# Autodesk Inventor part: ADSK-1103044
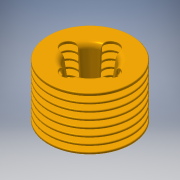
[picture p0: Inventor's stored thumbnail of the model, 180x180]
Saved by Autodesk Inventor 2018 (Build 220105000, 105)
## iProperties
Shininess: 41.0
Length Units: 11272
Angle Units: 11279
Time Units: 11290
Mass Units: 11286
Length Display Precision: 4
Angle Display Precision: 2
Compacted: True
Created: 2000-07
Part Number: ADSK-1103044
Document SubType Name: Modeling
Description: ENGINE HEAD
Mass: 37.1194 g
Surface Area: 215.954 cm^2
Volume: 13.6972 cm^3
Density: 2.71 g/cm^3
Material: Aluminum-6061
Appearance: Yellow
Density: 0.0
Volumn: 0.0
Area: 0.0
PropertySet Name: Model Information
Control State: 0
Master: False
Checked Out: False
Author: Autodesk, Inc.
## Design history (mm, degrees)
node "Revolution1" dims "d6" = 90 deg
  sketch "Sketch2"
    geometry: L1 (17.699, 35.694)-(17.699, 61.094); L2 (17.699, 61.094)-(-5.161, 61.094); L3 (-5.161, 31.884)-(2.459, 31.884); L4 (2.459, 31.884)-(2.459, 35.694); L5 (2.459, 35.694)-(17.699, 35.694); L6 (-5.161, 61.094)-(-5.161, 31.884)
    constraints: 12 end point, 4 perpendicular, 1 parallel, 1 vertical, 1 other
    dimensions: "d0" = 45.72 diameter of L2.end L1; "d1" = 30.48 diameter of L4 L1; "d3" = 29.21 distance between parallel lines of L2 L3; "d5" = 3.81 distance of L3.end L4.end
workaxis "Work Axis1"
workplane "Work Plane1"
workplane "Work Plane3"
node "Revolution2" dims "d12" = 90 deg
  sketch "Sketch3"
    geometry: L1 (0, -20.447)-(0, 20.447) reference; L2 (15.24, -10.795)-(-15.24, -10.795) reference; L3 (-5.999, -10.795)-(-5.999, -8.255); L4 (-5.999, -8.255)-(-7.938, -8.255); L5 (-7.938, -8.255)-(-11.15, 14.605); L6 (22.86, 14.605)-(-22.86, 14.605) reference; L7 (-5.999, -10.795)-(0, -10.795); L8 (-11.15, 14.605)-(0, 14.605); L9 (0, 14.605)-(0, -10.795)
    constraints: 12 end point, 3 perpendicular, 2 midpoint, 2 point on line
    dimensions: "d8" = 11.99896 diameter of L3 L1; "d9" = 2.54 distance between parallel lines of L2 L4; "d10" = 8 deg angle of L1 L5; "d11" = 15.875 diameter of L4.end L1
node "Fillet1" dims "d13" = 3.175
node "Extrusion1" dims "d16" = 25.4, "d17" = 0
  sketch "Sketch4" dims "d14" = 11.5
    geometry: C1 r 22.86 at (0, 0) reference; C2 r 13.91 at (0, 0) reference; C3 r 4.128 at (0, 11.5); 1 further point
    constraints: 2 vertical alignment, 1 centre point, 1 coincident, 2 other
    dimensions: "d15" = 8.255 diameter of C3
node "Circular Pattern1" dims "d18" = 40, "d20" = 90 deg
workplane "Work Plane2"
node "Revolution3" dims "d46" = 90 deg
  sketch "Sketch5"
    geometry: L1 (11.872, 10.766)-(-8.255, 7.938) reference; L2 (14.605, -22.86)-(14.605, 22.86) reference; L3 (-13.272, 25.4)-(-10.605, 25.4); L4 (-10.605, 25.4)-(-10.605, 16.906); L5 (-13.272, 16.906)-(-13.272, 25.4); L6 (-9.335, 25.4)-(-6.668, 25.4); L7 (-6.668, 25.4)-(-6.668, 10.16); L8 (-6.668, 10.16)-(-9.335, 10.16); L9 (-9.335, 10.16)-(-9.335, 25.4); L10 (-5.398, 25.4)-(-2.731, 25.4); L11 (-2.731, 25.4)-(-2.731, 10.477); L12 (-2.731, 10.477)-(-5.398, 10.477); L13 (-5.398, 10.477)-(-5.398, 25.4); L14 (-1.461, 25.4)-(1.206, 25.4); L15 (1.206, 25.4)-(1.206, 10.795); L16 (1.206, 10.795)-(-1.461, 10.795); L17 (-1.461, 10.795)-(-1.461, 25.4); L18 (2.476, 25.4)-(5.143, 25.4); L19 (5.143, 25.4)-(5.143, 11.112); L20 (5.143, 11.112)-(2.476, 11.112); L21 (2.476, 11.112)-(2.476, 25.4); L22 (6.413, 25.4)-(9.08, 25.4); L23 (9.08, 25.4)-(9.08, 11.43); L24 (9.08, 11.43)-(6.413, 11.43); L25 (6.413, 11.43)-(6.413, 25.4); L26 (10.35, 25.4)-(13.017, 25.4); L27 (13.017, 25.4)-(13.017, 11.747); L28 (13.017, 11.747)-(10.35, 11.747); L29 (10.35, 11.747)-(10.35, 25.4); L30 (-20.447, 0)-(20.447, 0) reference; L31 (-10.605, 16.906)-(-13.272, 16.906)
    constraints: 56 end point, 13 parallel, 8 perpendicular, 7 horizontal, 6 collinear, 6 point on line
    dimensions: "d22" = 2.667 distance between parallel lines of L27 L29; "d23" = 1.5875 distance between parallel lines of L2 L27; "d24" = 1.27 distance between parallel lines of L29 L23; "d25" = 1.27 distance between parallel lines of L25 L19 (= d24); "d26" = 1.27 distance between parallel lines of L21 L15 (= d24); "d27" = 1.27 distance between parallel lines of L17 L11 (= d29); "d28" = 1.27 distance between parallel lines of L7 L13; "d29" = 1.27 distance between parallel lines of L9 L4 (= d24); "d33" = 25.4 distance from line of L30 L26.end; "d38" = 0.3175 vertical distance of L7.end L12.end (= d37); "d39" = 0.3175 vertical distance of L11.end L16.end (= d38); "d40" = 0.3175 vertical distance of L15.end L19.end (= d39); "d41" = 0.3175 vertical distance of L19.end L23.end (= d40); "d42" = 0.3175 vertical distance of L23.end L27.end (= d41)
node "Extrusion2" dims "d48" = 1.5875, "d49" = 0
  sketch "Sketch6"
    geometry: A1 r 4.128 centre (0, 11.5) between (-3.609, 9.497) and (-1.721, 7.749) reference; 2 further points
    constraints: 1 coincident, 3 other
node "Circular Pattern3" dims "d61" = 40, "d63" = 360 deg
node "Fillet3" dims "d67" = 0.508
node "Fillet4" dims "d80" = 0.381
node "Fillet5" dims "d81" = 0.381
node "Hole1" dims "d50" = 2.90068, "d51" = 9.525, "d52" = 6.35, "d53" = 60 deg, "d54" = 19.05, "d55" = 118 deg, "d85" = 12.7
  sketch "Sketch7"
    geometry: C1 r 4.128 at (0, 0) reference
node "Circular Pattern4" dims "d64" = 40, "d66" = 360 deg
node "Fillet6" dims "d82" = 0.381
node "Fillet7" dims "d83" = 0.381
node "Fillet8" dims "d84" = 0.381
body "Solid1"
other parameters: "d7" = 0, "d21" = 45 deg, "d35" = 0.3175, "d36" = 0.3175 (= d35), "d37" = 0.3175 (= d36), "d95" = 90 deg
